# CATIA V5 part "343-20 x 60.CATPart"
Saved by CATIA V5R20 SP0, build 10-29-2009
Part number: 343-20 x 60
Definition: NONE
Nomenclature: 343-20 x 60
Source: Unknown
Description: 343-20 x 60
Bounding box of the stored display mesh (mm): x 0 to 60, y -15 to 15, z -15 to 15
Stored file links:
  C:\Users\Utente\Desktop\IO LAVORO\3D X SITO CF\X SITO\343-348\343-20 x 60.CATPart
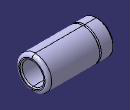
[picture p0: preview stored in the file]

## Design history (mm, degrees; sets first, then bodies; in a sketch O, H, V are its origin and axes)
Body1 "343-20 x 60" (main body)
  Solid1: solid without history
